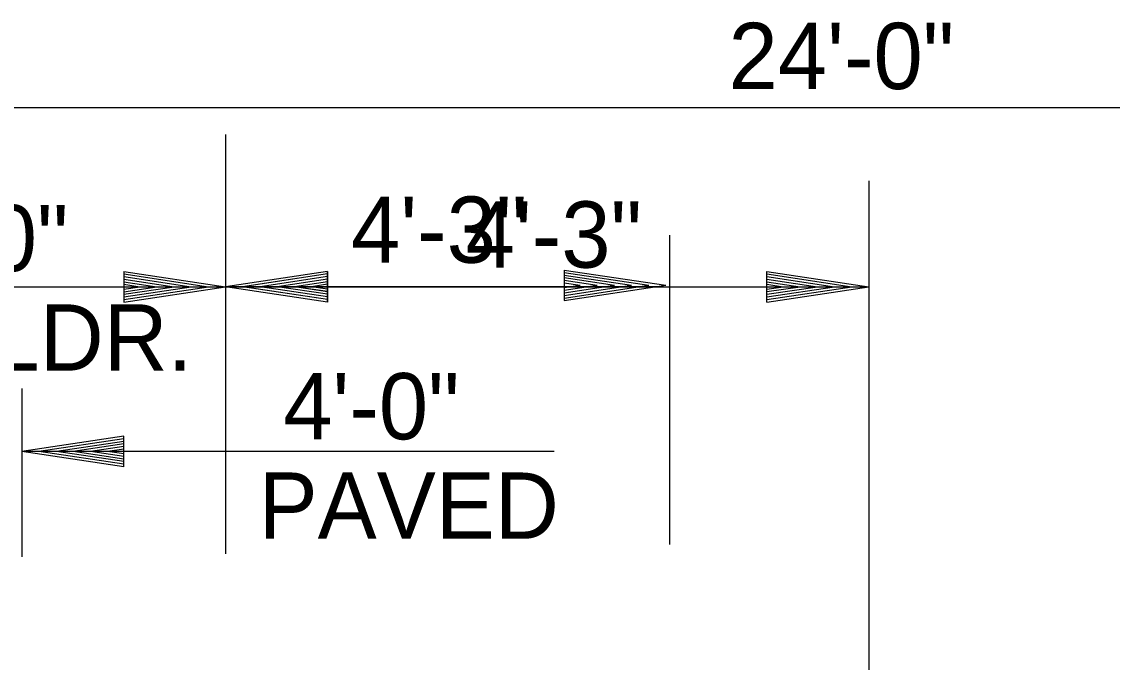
# Model space of a CAD drawing. Extents: x 1373719 to 1374161, y 379835 to 380167.
# Drawn here: x 1373977.71 to 1373988.41, y 380060.66 to 380066.95 of the extents above; entities that cross this region are included whole.
import ezdxf

# ---------------------------------------------------------------- set-up
doc = ezdxf.new("R2010")
doc.units = 0
doc.layers.add('GREEN_TXT', color=7, linetype='Continuous')
doc.layers.add('Text 1', color=7, linetype='Continuous')

msp = doc.modelspace()

# ---------------------------------------------------------------- linework, layer by layer
at = {"layer": 'GREEN_TXT'}
for p, q in [((1373975.718, 380066.104), (1373995.71, 380066.104)), ((1373979.715, 380065.84), (1373979.715, 380061.726)), ((1373986.027, 380065.385), (1373986.027, 380059.274)), ((1373978.715, 380064.497), (1373979.715, 380064.347)), ((1373978.715, 380064.497), (1373978.715, 380064.197)), ((1373980.714, 380064.497), (1373979.714, 380064.347)), ((1373980.714, 380064.497), (1373980.714, 380064.197)), ((1373985.027, 380064.497), (1373986.027, 380064.347)), ((1373985.027, 380064.197), (1373985.027, 380064.497)), ((1373978.715, 380064.472), (1373979.548, 380064.347)), ((1373978.715, 380064.447), (1373979.376, 380064.347)), ((1373978.715, 380064.422), (1373979.209, 380064.347)), ((1373978.715, 380064.396), (1373979.04, 380064.347)), ((1373980.714, 380064.472), (1373979.881, 380064.347)), ((1373980.714, 380064.447), (1373980.053, 380064.347)), ((1373980.714, 380064.422), (1373980.22, 380064.347)), ((1373980.714, 380064.396), (1373980.389, 380064.347)), ((1373985.027, 380064.472), (1373985.86, 380064.347)), ((1373985.027, 380064.447), (1373985.688, 380064.347)), ((1373985.027, 380064.422), (1373985.522, 380064.347)), ((1373985.027, 380064.396), (1373985.352, 380064.347)), ((1373975.715, 380064.347), (1373979.715, 380064.347)), ((1373978.715, 380064.371), (1373978.873, 380064.347)), ((1373978.715, 380064.197), (1373979.715, 380064.347)), ((1373978.715, 380064.298), (1373979.04, 380064.347)), ((1373978.715, 380064.248), (1373979.376, 380064.347)), ((1373978.715, 380064.222), (1373979.548, 380064.347)), ((1373978.715, 380064.273), (1373979.209, 380064.347)), ((1373978.715, 380064.324), (1373978.873, 380064.347)), ((1373979.714, 380064.347), (1373986.027, 380064.347)), ((1373980.714, 380064.197), (1373979.714, 380064.347)), ((1373980.714, 380064.222), (1373979.881, 380064.347)), ((1373980.714, 380064.248), (1373980.053, 380064.347)), ((1373980.714, 380064.273), (1373980.22, 380064.347)), ((1373980.714, 380064.298), (1373980.389, 380064.347)), ((1373980.714, 380064.371), (1373980.556, 380064.347)), ((1373980.714, 380064.324), (1373980.556, 380064.347)), ((1373985.027, 380064.371), (1373985.185, 380064.347)), ((1373985.027, 380064.197), (1373986.027, 380064.347)), ((1373985.027, 380064.299), (1373985.352, 380064.347)), ((1373985.027, 380064.248), (1373985.688, 380064.347)), ((1373985.027, 380064.222), (1373985.86, 380064.347)), ((1373985.027, 380064.273), (1373985.522, 380064.347)), ((1373985.027, 380064.324), (1373985.185, 380064.347))]:
    msp.add_line(p, q, dxfattribs=at)
at = {"layer": 'Text 1'}
for p, q in [((1373984.071, 380064.852), (1373984.071, 380061.819)), ((1373980.715, 380064.497), (1373979.715, 380064.347)), ((1373980.715, 380064.197), (1373980.715, 380064.497)), ((1373983.036, 380064.511), (1373984.036, 380064.361)), ((1373983.036, 380064.511), (1373983.036, 380064.211)), ((1373980.715, 380064.472), (1373979.882, 380064.347)), ((1373980.715, 380064.447), (1373980.054, 380064.347)), ((1373980.715, 380064.422), (1373980.22, 380064.347)), ((1373980.715, 380064.396), (1373980.39, 380064.347)), ((1373983.036, 380064.486), (1373983.869, 380064.361)), ((1373983.036, 380064.461), (1373983.697, 380064.361)), ((1373983.036, 380064.436), (1373983.53, 380064.361)), ((1373983.036, 380064.41), (1373983.361, 380064.361)), ((1373983.036, 380064.385), (1373983.194, 380064.361)), ((1373979.712, 380064.35), (1373983.962, 380064.35)), ((1373980.715, 380064.197), (1373979.715, 380064.347)), ((1373980.715, 380064.222), (1373979.882, 380064.347)), ((1373980.715, 380064.248), (1373980.054, 380064.347)), ((1373980.715, 380064.273), (1373980.22, 380064.347)), ((1373980.715, 380064.299), (1373980.39, 380064.347)), ((1373980.715, 380064.371), (1373980.557, 380064.347)), ((1373980.715, 380064.324), (1373980.557, 380064.347)), ((1373983.036, 380064.211), (1373984.036, 380064.361)), ((1373983.036, 380064.312), (1373983.361, 380064.361)), ((1373983.036, 380064.262), (1373983.697, 380064.361)), ((1373983.036, 380064.236), (1373983.869, 380064.361)), ((1373983.036, 380064.287), (1373983.53, 380064.361)), ((1373983.036, 380064.338), (1373983.194, 380064.361)), ((1373977.715, 380063.348), (1373977.715, 380061.699)), ((1373978.715, 380062.881), (1373977.715, 380062.731)), ((1373978.715, 380062.856), (1373977.882, 380062.731)), ((1373978.715, 380062.83), (1373978.054, 380062.731)), ((1373978.715, 380062.805), (1373978.22, 380062.731)), ((1373978.715, 380062.78), (1373978.39, 380062.731)), ((1373978.715, 380062.581), (1373978.715, 380062.881)), ((1373982.938, 380062.731), (1373977.715, 380062.731)), ((1373978.715, 380062.581), (1373977.715, 380062.731)), ((1373978.715, 380062.606), (1373977.882, 380062.731)), ((1373978.715, 380062.631), (1373978.054, 380062.731)), ((1373978.715, 380062.656), (1373978.22, 380062.731)), ((1373978.715, 380062.682), (1373978.39, 380062.731)), ((1373978.715, 380062.754), (1373978.557, 380062.731)), ((1373978.715, 380062.707), (1373978.557, 380062.731)), ((1373979.715, 380062.581), (1373979.715, 380061.726))]:
    msp.add_line(p, q, dxfattribs=at)

# ---------------------------------------------------------------- texts
at = {"layer": 'GREEN_TXT'}
for s, p in [('24\'-0"', (1373984.65, 380066.286)), (' 6\'-0"', (1373976.2, 380064.499)), ('4\'-3"', (1373982.07, 380064.534)), ('SHLDR.', (1373976.2, 380063.524))]:
    msp.add_text(s, height=0.65, dxfattribs=at).set_placement(p)
at = {"layer": 'Text 1'}
for s, p in [('4\'-3"', (1373980.945, 380064.582)), (' 4\'-0" ', (1373980.038, 380062.85)), ('PAVED', (1373980.038, 380061.875))]:
    msp.add_text(s, height=0.65, dxfattribs=at).set_placement(p)

doc.saveas('drawing.dxf')
